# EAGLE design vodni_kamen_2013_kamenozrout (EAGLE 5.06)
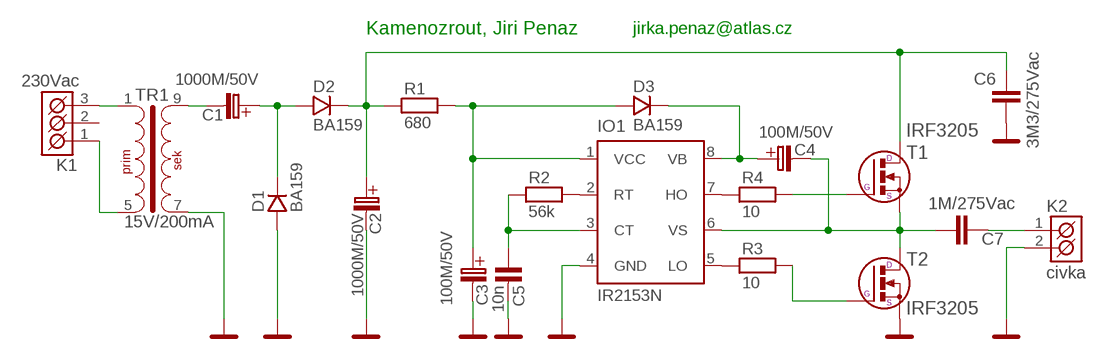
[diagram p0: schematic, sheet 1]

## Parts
C1  1000M/50V  [C_EL_7,5]
C2  1000M/50V  [C_EL_7,5]
C3  100M/50V  [C_EL_3,5]
C4  100M/50V  [C_EL_3,5]
C5  10n  C-KERAMIK_5  [C-5]
C6  3M3/275Vac  C27/11  [C27.5B11]
C7  1M/275Vac  C27/11  [C27.5B11]
D1  BA159  [DO41]
D2  BA159  [DO41]
D3  BA159  [DO41]
IO1  IR2153N  [DIP8]
K1  230Vac  ARK500/3  [ARK500/3]
K2  civka  ARK500/2  [ARK500/2]
R1  680  R_7,5  [R-7,5]
R2  56k  R_7,5  [R-7,5]
R3  10  R_7,5  [R-7,5]
R4  10  R_7,5  [R-7,5]
T1  IRF3205  BUZ11_LEZ  [TO-220]
T2  IRF3205  BUZ11_LEZ  [TO-220]
TR1  15V/200mA  TRHEI382-1  [TRHEI382]

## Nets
+30V: C2.C+(C_EL+) C6.1 D2.K R1.1 T1.2(D)
GND: C2.C-(C_EL-) C3.C-(C_EL-) C5.2 C6.2 D1.A IO1.4(GND) K2.2(K2) T2.3(S) TR1.7(S1)
N$1: IO1.7(HO) R4.1
N$2: IO1.2(RT) R2.2
N$3: C5.1 IO1.3(CT) R2.1
N$4: IO1.5(LO) R3.1
N$5: R3.2 T2.1(G)
N$6: R4.2 T1.1(G)
N$7: C4.C-(C_EL-) C7.1 IO1.6(VS) T1.3(S) T2.2(D)
N$8: C4.C+(C_EL+) D3.K IO1.8(VB)
N$9: C3.C+(C_EL+) D3.A IO1.1(VCC) R1.2
N$10: K1.3(K3) TR1.1
N$11: C1.C+(C_EL+) D1.K D2.A
N$13: K1.1(K1) TR1.5(P2)
N$14: C1.C-(C_EL-) TR1.9(S2)
N$15: C7.2 K2.1(K1)
Unconnected: K1.2(K2)

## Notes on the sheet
- Kamenozrout, Jiri Penaz | jirka.penaz@atlas.cz

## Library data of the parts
C1 C2 = #PaJa_C-el_2:1000M/50V
C3 C4 = #PaJa_C-el_2:100M/50V
C5 = #PaJa_31:C-KERAMIK: Kondenzator - keramicky
C6 C7 = capacitor-wima:C: CAPACITOR
D1-D3 = #PaJa_31:BA159: Rychlá dioda - 1A, 1000V
IO1 = Jan16:IR2153: IR2153 is a halfbridge driver with internal oscillator simillar to 555.
K1 = #PaJa_konektory:ARK500/3: Svorkovnice - roztec 5mm - trojita
K2 = #PaJa_konektory:ARK500/2: Svorkovnice - roztec 5mm - dvojita
R1-R4 = #PaJa_31:R: Rezistor
T1 T2 = #PaJa_31:BUZ11: N-Channel Enhancement MOSFET 50V; 20A; 0,080Ohm
TR1 = #PaJa_31:TRHEI382-1: Transformator - do DPS - 4,5 VA

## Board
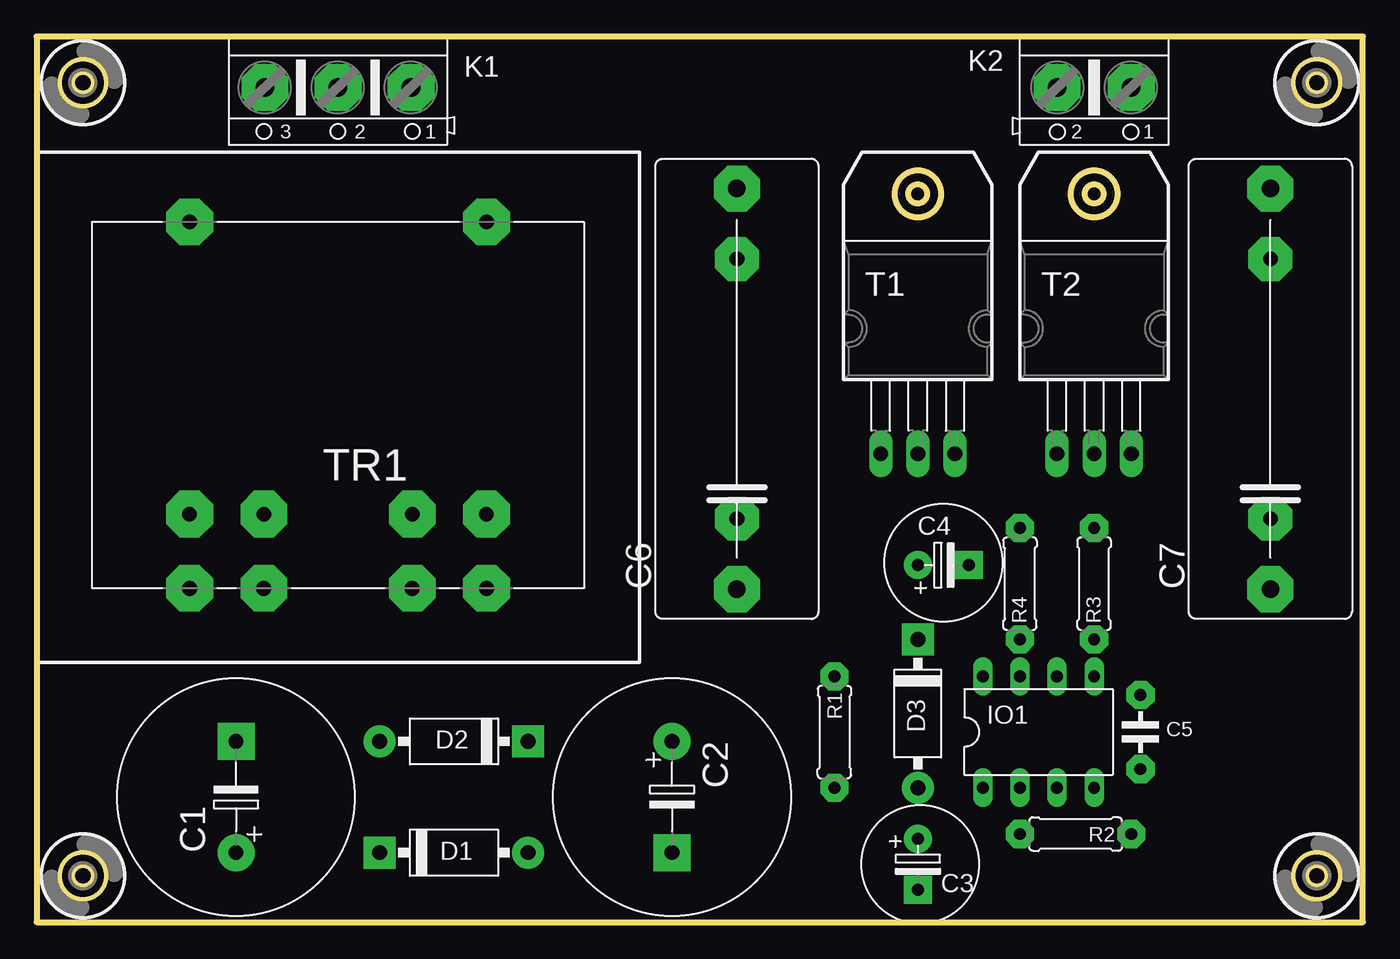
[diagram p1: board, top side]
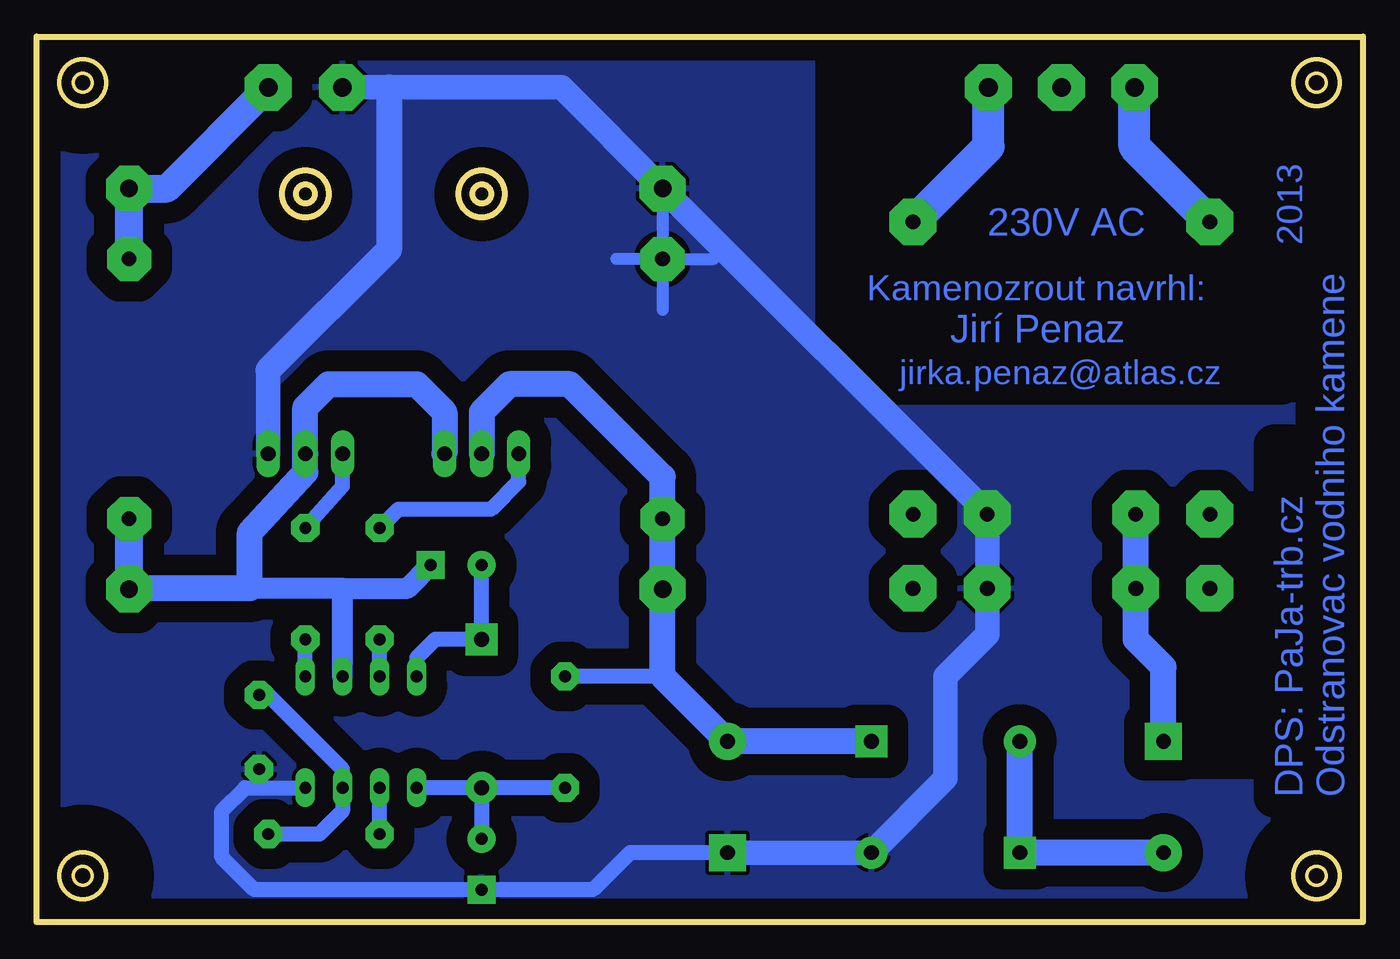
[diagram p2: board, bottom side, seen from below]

Size 90.79 x 60.63 mm. Coordinates in mm from the lower left corner, seen from the top.
Outline: 0,0 90.79,0 90.79,60.63 0,60.63 0,0
Outline: circle at 60.33,49.85 radius 0.64
Outline: circle at 72.39,49.85 radius 0.64
Outline: circle at 60.33,49.85 radius 1.59
Outline: circle at 72.39,49.85 radius 1.59
Copper layers (1*16): Top 0.035mm / dielectric 1.5mm / Bottom 0.035mm
Design rules "default": minimum track width 10mil, minimum drill 24mil, track to track 8mil, track to pad 8mil, pad to pad 8mil, via to via 8mil, smd to smd 8mil, copper to edge 40mil, drill to drill 8mil, minimum pad ring 10mil, minimum via ring 8mil, stop-mask expansion 4mil, vias tented up to drill 0mil, thermal gap 10mil
bRestrict: area 47.6,45.1 to 48.3,45.7; 3 lines

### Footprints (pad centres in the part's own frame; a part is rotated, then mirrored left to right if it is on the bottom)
C_EL_7,5 = drill 1.016 pad 2.54 round: C+ -3.81,0 | drill 1.016 pad 2.54 square: C- 3.81,0
C_EL_3,5 = drill 0.813 pad 1.93 round: C+ 0,0 | drill 0.813 pad 1.93 square: C- 3.493,0
C-5 = drill 0.813 pad 1.93 octagon: 1 -2.54,0; 2 2.54,0
C27.5B11 = drill 1.194 pad 3.15 octagon: 1 -13.716,0; 2 13.716,0
DO41 = drill 1.016 pad 2.184 round: A -5.08,0 | drill 1.016 pad 2.184 square: K 5.08,0
DIP8 = drill 0.813 long: 1 -3.81,-3.81; 2 -1.27,-3.81; 3 1.27,-3.81; 4 3.81,-3.81; 5 3.81,3.81; 6 1.27,3.81; 7 -1.27,3.81; 8 -3.81,3.81
ARK500/3 = drill 1.27 pad 3.2 octagon: 1 -5,0; 2 0,0; 3 5,0
ARK500/2 = drill 1.27 pad 3.2 octagon: 1 -2.54,0; 2 2.54,0
R-7,5 = drill 0.813 pad 1.93 octagon: 1 -3.81,0; 2 3.81,0
TO-220 = drill 1.016 pad 1.6 long: 1 -2.54,0; 2 0,0; 3 2.54,0
TRHEI382 = drill 1.016 pad 3.2 octagon: 1 -10.16,12.7; 5 10.16,12.7; 6 10.16,-12.383; 7 5.08,-12.383; 9 -5.08,-12.383; 10 -10.16,-12.383
HOLE_3,0 = hole 3.2: 0,0

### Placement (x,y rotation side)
C1  13.65,8.57 90 top
C2  43.5,8.57 270 top
C3  60.33,5.71 270 top
C4  60.33,24.45 0 top
C5  75.56,13.02 270 top
C6  47.94,36.51 90 top
C7  84.45,36.51 90 top
D1  28.57,4.76 180 top
D2  28.57,12.38 0 top
D3  60.33,14.29 90 top
IO1  68.58,13.02 0 top
K1  20.64,57.15 180 top
K2  72.39,57.15 180 top
R1  54.61,13.02 270 top
R2  71.12,6.03 180 top
R3  72.39,23.18 90 top
R4  67.31,23.18 90 top
T1  60.33,32.07 0 top
T2  72.39,32.07 0 top
TR1  20.64,35.24 0 top
U$1  [HOLE_3,0]  3.17,3.17 0 top
U$2  [HOLE_3,0]  87.63,3.17 0 top
U$3  [HOLE_3,0]  87.63,57.47 0 top
U$4  [HOLE_3,0]  3.17,57.47 0 top

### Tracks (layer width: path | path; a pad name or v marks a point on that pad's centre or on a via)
+30V  (via drill 1 pad 3)
  Bottom 1.016: 47.94,16.83 R1.1
  Bottom 1.778: D2.K C2.C+ 47.94,16.83 C6.1 v47.94,27.62 47.94,30.48 54.29,36.83 58.42,36.83 60.33,34.92 T1.2
GND  (via drill 1 pad 3, 1 pad 3.2)
  Bottom 0.813: C6.2 v47.94,45.4 | v47.94,45.4 47.94,41.91 | v47.94,45.4 51.12,45.4 | v47.94,45.4 44.45,45.4
  Bottom 1.016: C2.C- 50.16,4.76 52.7,2.22 C3.C- 75.88,2.22 78.11,4.45 78.11,7.62 76.52,9.21 75.56,9.21 | 75.56,9.21 IO1.4 | 75.56,9.21 C5.2
  Bottom 1.676: K2.2 66.67,57.15 54.86,57.15 C6.2 25.72,28 v25.72,27.94 TR1.7 25.72,19.68 28.57,16.83 28.57,9.84 D1.A C2.C- | 74.93,37.78 T2.3
  Bottom 1.778: 74.93,37.78 66.67,46.04 66.67,57.15
  pour Bottom (isolate 1.422): 0,0 0,60.64 90.81,60.64 90.81,0
N$1
  Bottom 1.016: IO1.7 R4.1
N$2
  Bottom 1.016: R2.2 IO1.2
N$3
  Bottom 1.016: R2.1 71.44,6.03 69.85,7.62 IO1.3 69.85,10.48 74.93,15.56 C5.1
N$4
  Bottom 1.016: IO1.5 R3.1
N$5
  Bottom 1.016: R3.2 69.85,29.84 T2.1
N$6
  Bottom 1.016: T1.1 57.78,30.16 59.69,28.26 66.04,28.26 R4.2
N$7  (via drill 1 pad 3)
  Bottom 1.422: 69.85,22.86 76.2,22.86 | IO1.6 69.85,22.86 | C4.C- 65.41,22.86 69.85,22.86 | 84.39,22.86 C7.1
  Bottom 1.778: T1.3 62.87,34.92 64.77,36.83 70.8,36.83 72.39,35.24 T2.2 72.39,30.8 76.2,26.67 76.2,22.86 84.39,22.86
  Bottom 1.93: C7.1 v84.45,27.62
N$8
  Bottom 1.016: C4.C+ D3.K 63.5,19.37 64.77,18.1 IO1.8
N$9
  Bottom 1.016: R1.2 D3.A | D3.A C3.C+ | D3.A IO1.1
N$10
  Bottom 2.184: K1.3 15.64,53.1 TR1.1
N$11
  Bottom 1.778: C1.C+ D1.K D2.A
N$12  (via drill 1 pad 3.2)
  other vias: 10.48,27.94
N$13
  Bottom 2.184: K1.1 25.64,53.1 TR1.5
N$14  (via drill 1 pad 3.2)
  Bottom 1.778: C1.C- 13.65,17.46 15.56,19.37 TR1.9 v15.56,27.94
N$15  (via drill 1 pad 3)
  Bottom 1.93: K2.1 81.85,50.23 C7.2 v84.45,45.4
N$17  (via drill 1 pad 3.2)
  other vias: 30.8,27.94

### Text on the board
Bottom: 230V AC | 2013 | Kamenozrout navrhl: | Jirí Penaz | jirka.penaz@atlas.cz | Odstranovac vodniho kamene | DPS: PaJa-trb.cz
PaJa: www.paja-trb.cz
